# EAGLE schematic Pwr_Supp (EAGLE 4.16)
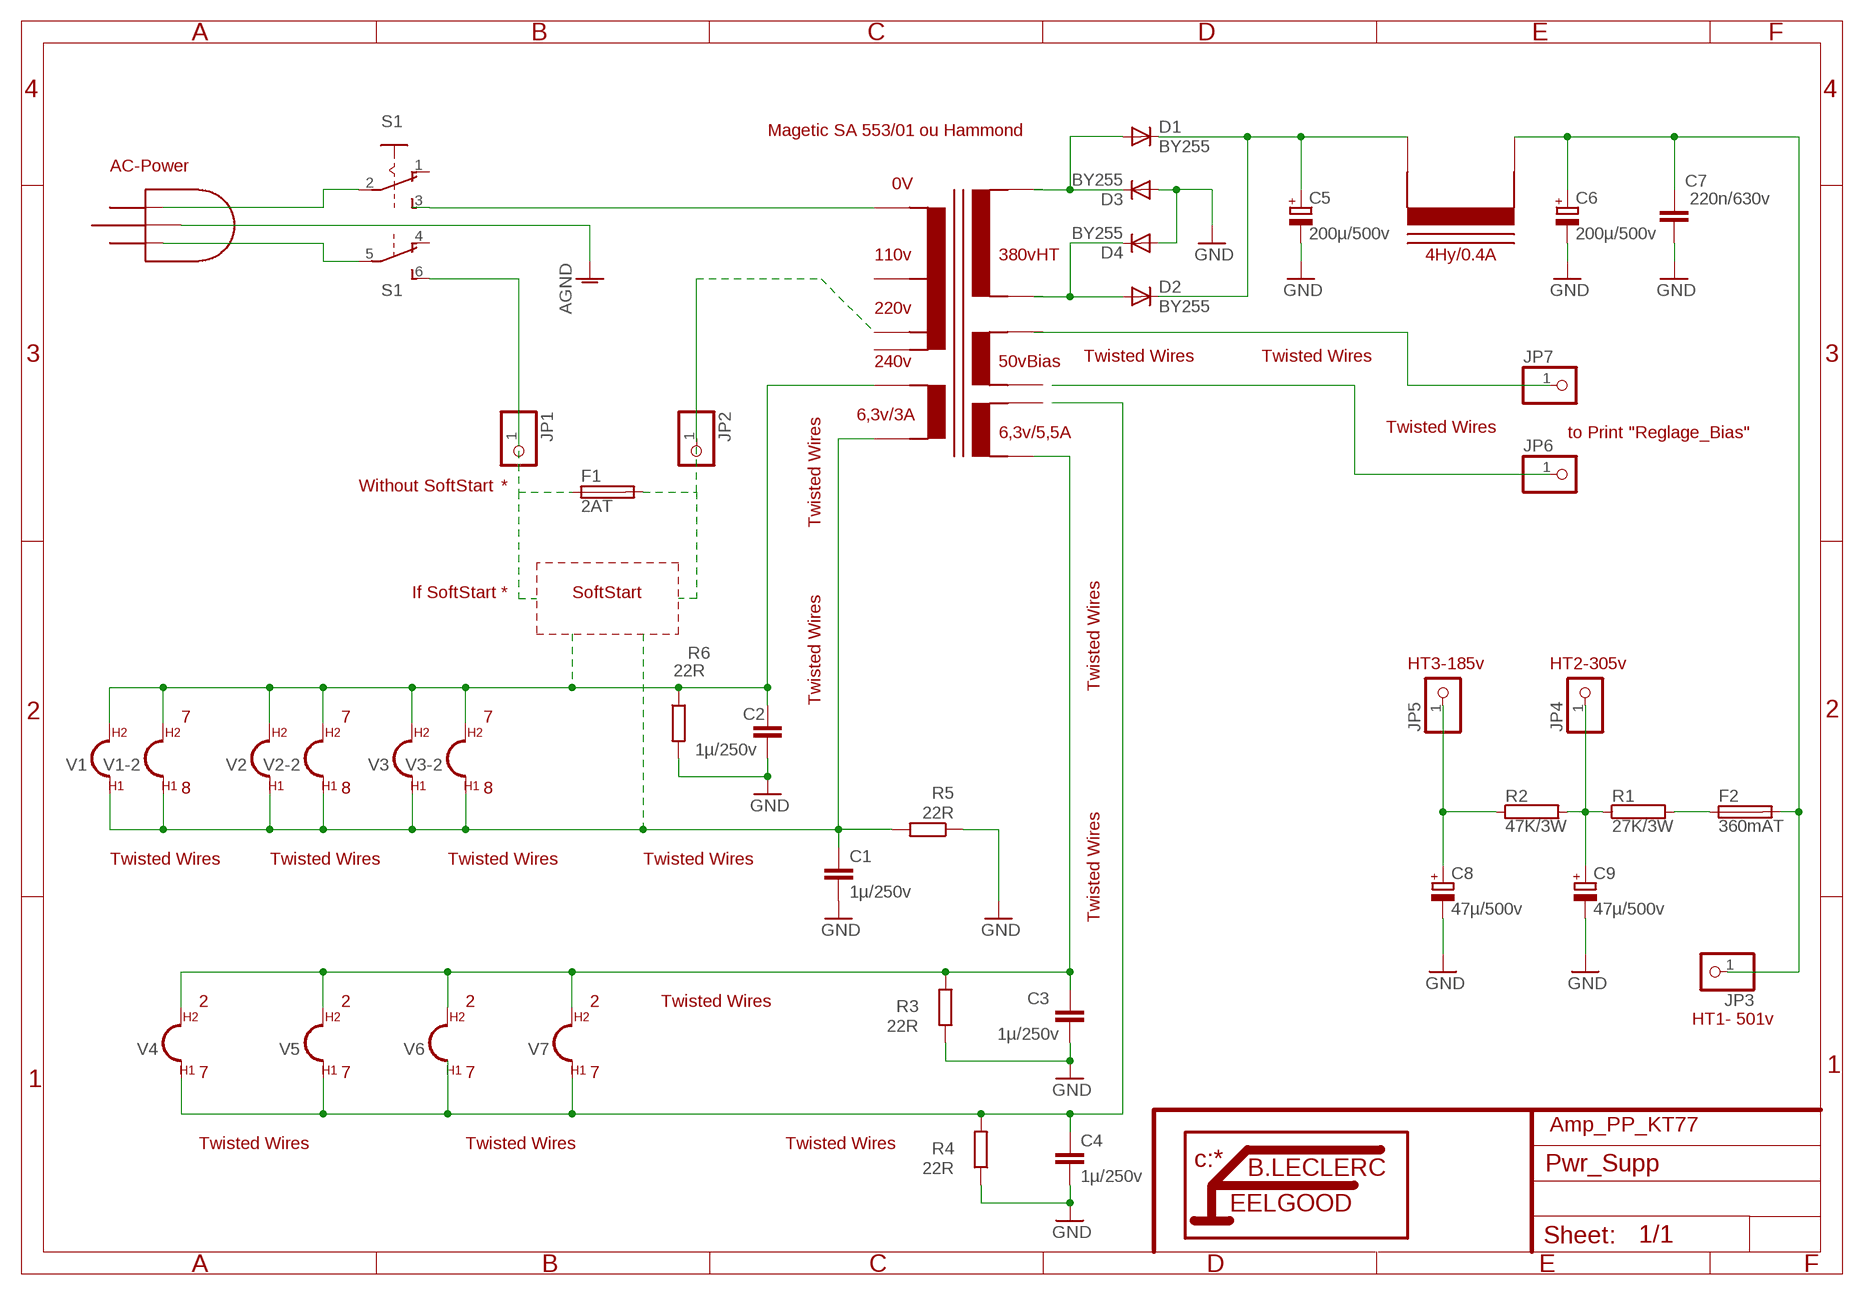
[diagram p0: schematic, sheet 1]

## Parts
C1  1µ/250v  C-EU102-043X133  [C102-043X133]
C2  1µ/250v  C-EU102-043X133  [C102-043X133]
C3  1µ/250v  C-EU102-043X133  [C102-043X133]
C4  1µ/250v  C-EU102-043X133  [C102-043X133]
C5  200µ/500v  CPOL-EUE10-35  [EB35D]
C6  200µ/500v  CPOL-EUE10-35  [EB35D]
C7  220n/630v  C-EU102-043X133  [C102-043X133]
C8  47µ/500v  CPOL-EUE10-35  [EB35D]
C9  47µ/500v  CPOL-EUE10-35  [EB35D]
D1  BY255  BYT03  [DO27-15]
D2  BY255  BYT03  [DO27-15]
D3  BY255  BYT03  [DO27-15]
D4  BY255  BYT03  [DO27-15]
F1  2AT  FUSESH22,5  [SH22,5]
F2  360mAT  FUSESH22,5  [SH22,5]
JP1  PINHD-1X1  [1X01]
JP2  PINHD-1X1  [1X01]
JP3  PINHD-1X1  [1X01]
JP4  PINHD-1X1  [1X01]
JP5  PINHD-1X1  [1X01]
JP6  PINHD-1X1  [1X01]
JP7  PINHD-1X1  [1X01]
R1  27K/3W  RKH206-8  [KH206-8]
R2  47K/3W  RKH206-8  [KH206-8]
R3  22R  R-EU_0207/10  [0207/10]
R4  22R  R-EU_0207/10  [0207/10]
R5  22R  R-EU_0207/10  [0207/10]
R6  22R  R-EU_0207/10  [0207/10]
S1  A68-A31  [A68-A31]
U$2  PWR_AUDIO  [PWR_AUDIO]
U$3  PLUG_AC  [PLUG_AC]
U$4  SLF_AUDIO  [SLF_AUDIO]

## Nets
AGND: U$3.P$3
GND: C1.2 C2.2 C3.2 C4.2 C5.- C6.- C7.2 C8.- C9.- D3.A D4.A R3.1 R4.1 R5.1 R6.2
N$1: S1.3(A:S) U$2.P$1(PRI_0V)
N$2: F1.1 JP1.1 S1.6(B:S)
N$3: JP2.1 U$2.P$3(PRI_220)
N$4: F1.2
N$5: S1.2(A:P) U$3.P$1
N$6: S1.5(B:P) U$3.P$2
N$7: C1.1 R5.2 U$2.P$5(F_PRE1)
N$8: C2.1 R6.1 U$2.P$6(F_PRÉ)
N$9: C3.1 R3.2
N$10: C4.1 R4.2
N$11: D2.A D4.C
N$12: C6.+ C7.1 F2.2 JP3.1 U$4.P$1
N$13: D1.A D3.C
N$14: C5.+ D1.C D2.C U$4.P$2
N$15: F2.1 R1.2
N$16: C9.+ JP4.1 R1.1 R2.2
N$17: C8.+ JP5.1 R2.1
N$18: JP7.1
N$19: JP6.1
Unconnected: S1.1(A:O) S1.4(B:O) U$2.P$2(PRI_110) U$2.P$4(PRI_240) U$2.P$7(HT) U$2.P$8(HT1) U$2.P$9(BIAS) U$2.P$10(BIAS1) U$2.P$11(F_PWR) U$2.P$12(F_PWR1)

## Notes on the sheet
- Magetic SA 553/01 ou Hammond
- AC-Power
- 4Hy/0.4A
- Twisted Wires | Twisted Wires
- Twisted Wires
- to Print "Reglage_Bias"
- Without SoftStart | *
- Twisted Wires
- Twisted Wires
- If SoftStart | * | SoftStart
- HT3-185v | HT2-305v
- Twisted Wires
- 7 | 7 | 7
- 8 | 8 | 8
- Twisted Wires
- Twisted Wires | Twisted Wires | Twisted Wires | Twisted Wires
- 2 | 2 | 2 | 2 | Twisted Wires
- HT1- 501v
- 7 | 7 | 7 | 7
- Amp_PP_KT77
- Twisted Wires | Twisted Wires | Twisted Wires

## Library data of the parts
C1-C4 C7 = rcl:C-EU: CAPACITOR, European symbol
C5 C6 C8 C9 = rcl:CPOL-EU: POLARIZED CAPACITOR, European symbol
D1-D4 = diode:BYT03: DIODE
F1 F2 = fuse:FUSE: Fuse
JP1-JP7 = pinhead:PINHD-1X1: PIN HEADER
R1 R2 = resistor-power:R: Power Resitor
R3-R6 = rcl:R-EU_: RESISTOR, European symbol
S1 = switch:A68-A31: SLIDING SWITCH Siemens, distributor Buerklin, 11G766
U$2 = trafo:PWR_AUDIO
U$3 = supply2:PLUG_AC
U$4 = trafo:SLF_AUDIO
